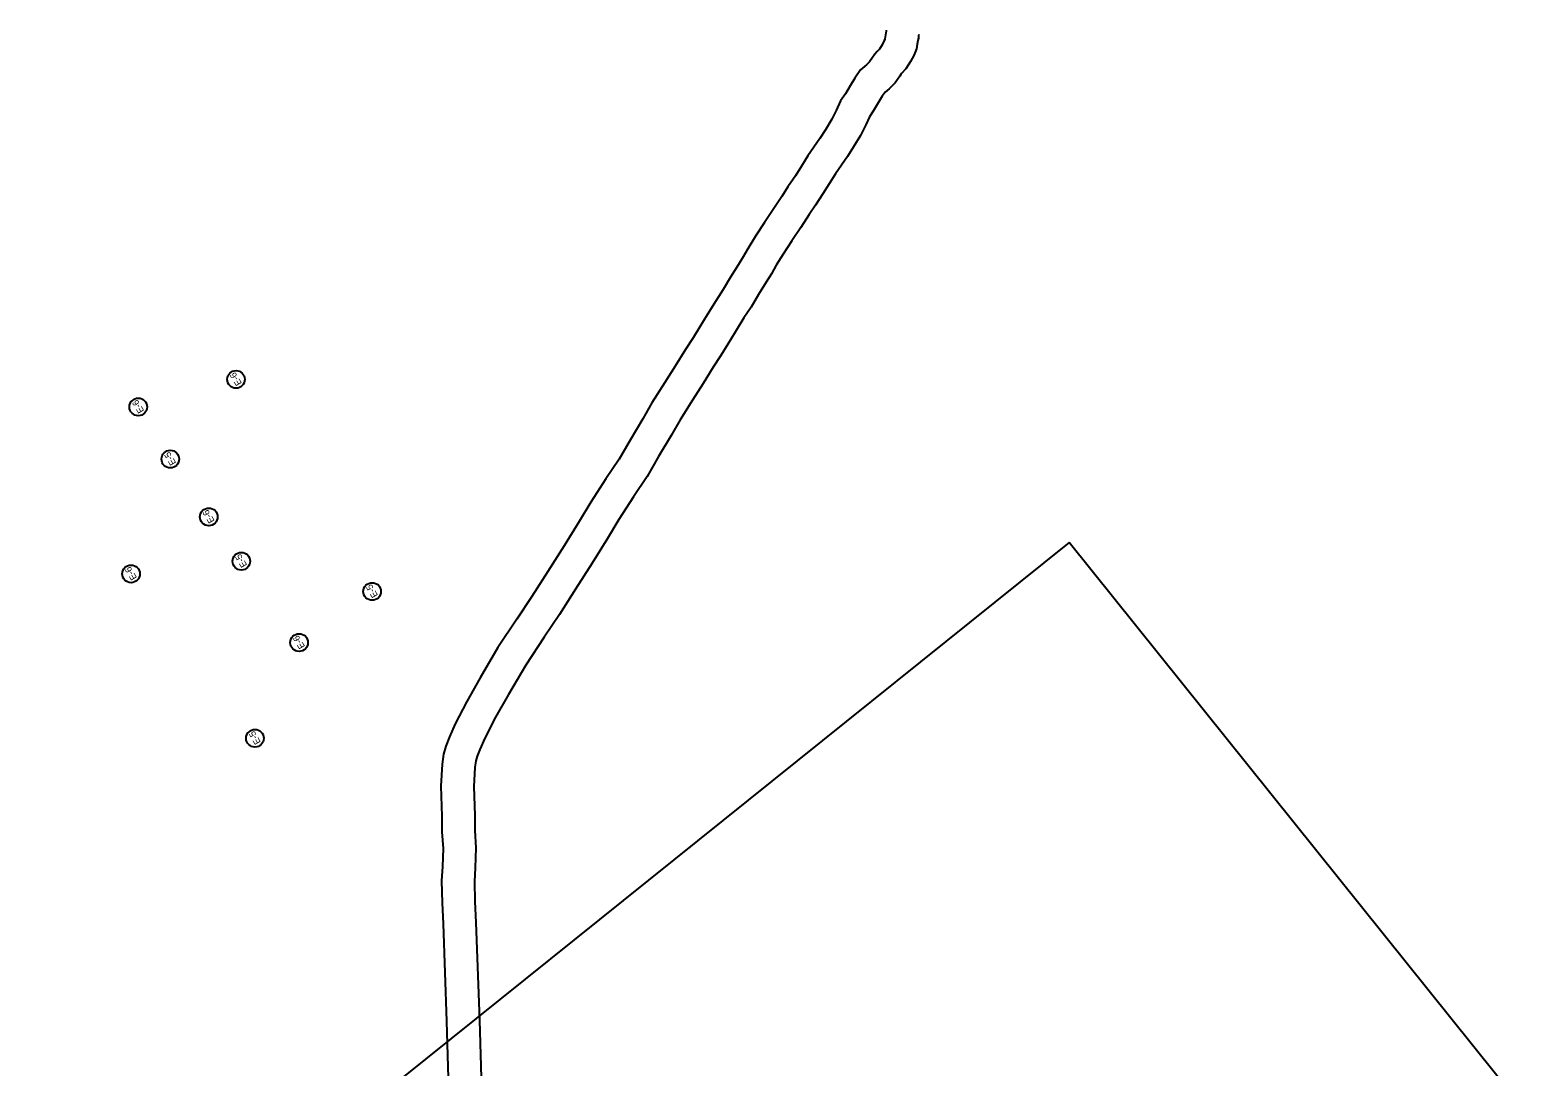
# Model space of a CAD drawing. Extents: x 641687 to 655797, y 406445 to 431088.
# Drawn here: x 646653 to 648945, y 421077 to 422652 of the extents above; entities that cross this region are included whole.
import ezdxf

# ---------------------------------------------------------------- set-up
doc = ezdxf.new("R2010")
doc.units = 0
for name, color, linetype in [('R_Erosion', 7, 'Continuous'), ('R_Erosion_Buffer', 7, 'Continuous'), ('R_No Plot', 7, 'Continuous')]:
    doc.layers.add(name, color=color, linetype=linetype)

msp = doc.modelspace()

# ---------------------------------------------------------------- linework, layer by layer
at = {"layer": 'R_Erosion'}
for centre in [(646965.9, 422121.5), (646817.3, 422079.7), (646866, 422000.4), (646924.5, 421912.6), (646974, 421845.2), (646806.3, 421826), (647172.8, 421799.2), (647061.8, 421721.6), (646994.7, 421576.2)]:
    msp.add_circle(centre, 13.4, dxfattribs=at)
at = {"layer": 'R_Erosion_Buffer'}
for points in [[(647954.3, 422652.2), (647954.1, 422650.2), (647953.8, 422648.4), (647953.2, 422645), (647952.3, 422639.2), (647952.1, 422638.1), (647950.9, 422635.4), (647948.1, 422630), (647943.9, 422623.5), (647940.7, 422619.8), (647936.9, 422615.8), (647933.6, 422610.6), (647929.1, 422604.3), (647924.4, 422599.5), (647915.4, 422591.8), (647906.6, 422579.4), (647899.3, 422567.6), (647892.2, 422555.6), (647885, 422544.7), (647878.3, 422530.1), (647871.6, 422516.9), (647861.8, 422501), (647853.5, 422487.5), (647835.4, 422461.4), (647825.4, 422445.3), (647816.2, 422431), (647804.9, 422413.9), (647795.4, 422399.4), (647782.6, 422379.8), (647769.5, 422359.7), (647755.6, 422339.2), (647743.8, 422320.1), (647737, 422307.6), (647729.6, 422296.1), (647717.6, 422276.7), (647706.3, 422257.9), (647695.8, 422241.6), (647682.3, 422219.7), (647671, 422201.3), (647660.7, 422184.8), (647649.1, 422167), (647633.6, 422141.8), (647617.7, 422116.8), (647598.2, 422085.7), (647584.2, 422061.5), (647565.1, 422029.4), (647548.3, 422000.5), (647528.2, 421970.6), (647505.2, 421935.1), (647487.7, 421905.5), (647464.8, 421868.8), (647439.9, 421829.8), (647415.6, 421791.8), (647392.8, 421757.3), (647364.1, 421714), (647336.8, 421668), (647316.6, 421632.1), (647299, 421598.1), (647290.3, 421578.5), (647284.7, 421564.3), (647281.5, 421551.8), (647279.2, 421536.7), (647277.5, 421503.6), (647278.7, 421457.9), (647278.9, 421433.8), (647280.7, 421408.8), (647279.6, 421381.5), (647278.3, 421359.4), (647279.2, 421326.2), (647280.6, 421294.3), (647286.1, 421146.2), (647289.9, 421008.1)], [(647954.3, 422652.2), (647954.1, 422650.2), (647953.8, 422648.4), (647953.2, 422645), (647952.3, 422639.2), (647952.1, 422638.1), (647950.9, 422635.4), (647948.1, 422630), (647943.9, 422623.5), (647940.7, 422619.8), (647936.9, 422615.8), (647933.6, 422610.6), (647929.1, 422604.3), (647924.4, 422599.5), (647915.4, 422591.8), (647906.6, 422579.4), (647899.3, 422567.6), (647892.2, 422555.6), (647885, 422544.7), (647878.3, 422530.1), (647871.6, 422516.9), (647861.8, 422501), (647853.5, 422487.5), (647835.4, 422461.4), (647825.4, 422445.3), (647816.2, 422431), (647804.9, 422413.9), (647795.4, 422399.4), (647782.6, 422379.8), (647769.5, 422359.7), (647755.6, 422339.2), (647743.8, 422320.1), (647737, 422307.6), (647729.6, 422296.1), (647717.6, 422276.7), (647706.3, 422257.9), (647695.8, 422241.6), (647682.3, 422219.7), (647671, 422201.3), (647660.7, 422184.8), (647649.1, 422167), (647633.6, 422141.8), (647617.7, 422116.8), (647598.2, 422085.7), (647584.2, 422061.5), (647565.1, 422029.4), (647548.3, 422000.5), (647528.2, 421970.6), (647505.2, 421935.1), (647487.7, 421905.5), (647464.8, 421868.8), (647439.9, 421829.8), (647415.6, 421791.8), (647392.8, 421757.3), (647364.1, 421714), (647336.8, 421668), (647316.6, 421632.1), (647299, 421598.1), (647290.3, 421578.5), (647284.7, 421564.3), (647281.5, 421551.8), (647279.2, 421536.7), (647277.5, 421503.6), (647278.7, 421457.9), (647278.9, 421433.8), (647280.7, 421408.8), (647279.6, 421381.5), (647278.3, 421359.4), (647279.2, 421326.2), (647280.6, 421294.3), (647286.1, 421146.2), (647289.9, 421008.1)], [(647954.3, 422652.2), (647954.1, 422650.2), (647953.8, 422648.4), (647953.2, 422645), (647952.3, 422639.2), (647952.1, 422638.1), (647950.9, 422635.4), (647948.1, 422630), (647943.9, 422623.5), (647940.7, 422619.8), (647936.9, 422615.8), (647933.6, 422610.6), (647929.1, 422604.3), (647924.4, 422599.5), (647915.4, 422591.8), (647906.6, 422579.4), (647899.3, 422567.6), (647892.2, 422555.6), (647885, 422544.7), (647878.3, 422530.1), (647871.6, 422516.9), (647861.8, 422501), (647853.5, 422487.5), (647835.4, 422461.4), (647825.4, 422445.3), (647816.2, 422431), (647804.9, 422413.9), (647795.4, 422399.4), (647782.6, 422379.8), (647769.5, 422359.7), (647755.6, 422339.2), (647743.8, 422320.1), (647737, 422307.6), (647729.6, 422296.1), (647717.6, 422276.7), (647706.3, 422257.9), (647695.8, 422241.6), (647682.3, 422219.7), (647671, 422201.3), (647660.7, 422184.8), (647649.1, 422167), (647633.6, 422141.8), (647617.7, 422116.8), (647598.2, 422085.7), (647584.2, 422061.5), (647565.1, 422029.4), (647548.3, 422000.5), (647528.2, 421970.6), (647505.2, 421935.1), (647487.7, 421905.5), (647464.8, 421868.8), (647439.9, 421829.8), (647415.6, 421791.8), (647392.8, 421757.3), (647364.1, 421714), (647336.8, 421668), (647316.6, 421632.1), (647299, 421598.1), (647290.3, 421578.5), (647284.7, 421564.3), (647281.5, 421551.8), (647279.2, 421536.7), (647277.5, 421503.6), (647278.7, 421457.9), (647278.9, 421433.8), (647280.7, 421408.8), (647279.6, 421381.5), (647278.3, 421359.4), (647279.2, 421326.2), (647280.6, 421294.3), (647286.1, 421146.2), (647289.9, 421008.1)], [(648003.9, 422645.6), (648003.6, 422643.6), (648003.2, 422640.3), (648002.4, 422636.5), (648001.6, 422630.9), (648000.2, 422623.6), (647996.2, 422613.9), (647991.3, 422604.8), (647984.1, 422593.5), (647977.7, 422586.2), (647976.3, 422584.7), (647974.9, 422582.5), (647967.8, 422572.4), (647958.7, 422563), (647952.6, 422557.8), (647948.3, 422551.7), (647942.1, 422541.7), (647934.7, 422529.1), (647928.9, 422520.3), (647923.3, 422508.2), (647915.2, 422492.4), (647904.4, 422474.8), (647895.4, 422460.2), (647877.3, 422434.1), (647867.7, 422418.5), (647858, 422403.6), (647846.7, 422386.5), (647837.2, 422372), (647824.4, 422352.4), (647811.1, 422332), (647797.6, 422312), (647787.1, 422295.1), (647780, 422282), (647771.8, 422269.4), (647760.4, 422250.7), (647748.8, 422231.4), (647738, 422214.9), (647724.9, 422193.5), (647713.5, 422175), (647702.9, 422158), (647691.4, 422140.3), (647676, 422115.3), (647660, 422090.1), (647641, 422059.9), (647627.3, 422036.2), (647608.2, 422004.1), (647590.8, 421974), (647570, 421943), (647547.7, 421908.7), (647530.5, 421879.6), (647507.1, 421842.1), (647482, 421802.9), (647457.6, 421764.5), (647434.5, 421729.7), (647406.5, 421687.4), (647380.1, 421642.9), (647360.6, 421608.4), (647344.1, 421576.4), (647336.4, 421559.2), (647332.4, 421548.9), (647330.5, 421541.7), (647329, 421531.6), (647327.6, 421503), (647328.7, 421458.7), (647328.9, 421435.8), (647330.7, 421409.7), (647329.6, 421379.1), (647328.4, 421358.5), (647329.1, 421328), (647330.6, 421296.4), (647336.1, 421147.8), (647340, 421008.1)], [(648003.9, 422645.6), (648003.6, 422643.6), (648003.2, 422640.3), (648002.4, 422636.5), (648001.6, 422630.9), (648000.2, 422623.6), (647996.2, 422613.9), (647991.3, 422604.8), (647984.1, 422593.5), (647977.7, 422586.2), (647976.3, 422584.7), (647974.9, 422582.5), (647967.8, 422572.4), (647958.7, 422563), (647952.6, 422557.8), (647948.3, 422551.7), (647942.1, 422541.7), (647934.7, 422529.1), (647928.9, 422520.3), (647923.3, 422508.2), (647915.2, 422492.4), (647904.4, 422474.8), (647895.4, 422460.2), (647877.3, 422434.1), (647867.7, 422418.5), (647858, 422403.6), (647846.7, 422386.5), (647837.2, 422372), (647824.4, 422352.4), (647811.1, 422332), (647797.6, 422312), (647787.1, 422295.1), (647780, 422282), (647771.8, 422269.4), (647760.4, 422250.7), (647748.8, 422231.4), (647738, 422214.9), (647724.9, 422193.5), (647713.5, 422175), (647702.9, 422158), (647691.4, 422140.3), (647676, 422115.3), (647660, 422090.1), (647641, 422059.9), (647627.3, 422036.2), (647608.2, 422004.1), (647590.8, 421974), (647570, 421943), (647547.7, 421908.7), (647530.5, 421879.6), (647507.1, 421842.1), (647482, 421802.9), (647457.6, 421764.5), (647434.5, 421729.7), (647406.5, 421687.4), (647380.1, 421642.9), (647360.6, 421608.4), (647344.1, 421576.4), (647336.4, 421559.2), (647332.4, 421548.9), (647330.5, 421541.7), (647329, 421531.6), (647327.6, 421503), (647328.7, 421458.7), (647328.9, 421435.8), (647330.7, 421409.7), (647329.6, 421379.1), (647328.4, 421358.5), (647329.1, 421328), (647330.6, 421296.4), (647336.1, 421147.8), (647340, 421008.1)], [(648003.9, 422645.6), (648003.6, 422643.6), (648003.2, 422640.3), (648002.4, 422636.5), (648001.6, 422630.9), (648000.2, 422623.6), (647996.2, 422613.9), (647991.3, 422604.8), (647984.1, 422593.5), (647977.7, 422586.2), (647976.3, 422584.7), (647974.9, 422582.5), (647967.8, 422572.4), (647958.7, 422563), (647952.6, 422557.8), (647948.3, 422551.7), (647942.1, 422541.7), (647934.7, 422529.1), (647928.9, 422520.3), (647923.3, 422508.2), (647915.2, 422492.4), (647904.4, 422474.8), (647895.4, 422460.2), (647877.3, 422434.1), (647867.7, 422418.5), (647858, 422403.6), (647846.7, 422386.5), (647837.2, 422372), (647824.4, 422352.4), (647811.1, 422332), (647797.6, 422312), (647787.1, 422295.1), (647780, 422282), (647771.8, 422269.4), (647760.4, 422250.7), (647748.8, 422231.4), (647738, 422214.9), (647724.9, 422193.5), (647713.5, 422175), (647702.9, 422158), (647691.4, 422140.3), (647676, 422115.3), (647660, 422090.1), (647641, 422059.9), (647627.3, 422036.2), (647608.2, 422004.1), (647590.8, 421974), (647570, 421943), (647547.7, 421908.7), (647530.5, 421879.6), (647507.1, 421842.1), (647482, 421802.9), (647457.6, 421764.5), (647434.5, 421729.7), (647406.5, 421687.4), (647380.1, 421642.9), (647360.6, 421608.4), (647344.1, 421576.4), (647336.4, 421559.2), (647332.4, 421548.9), (647330.5, 421541.7), (647329, 421531.6), (647327.6, 421503), (647328.7, 421458.7), (647328.9, 421435.8), (647330.7, 421409.7), (647329.6, 421379.1), (647328.4, 421358.5), (647329.1, 421328), (647330.6, 421296.4), (647336.1, 421147.8), (647340, 421008.1)]]:
    msp.add_lwpolyline(points, dxfattribs=at)
at = {"layer": 'R_No Plot'}
msp.add_lwpolyline([(648232.3, 421873.9), (646652.9, 420606.2), (646652.9, 420606.2), (648155.3, 418734.6), (649734.6, 420002.3)], close=True, dxfattribs=at)

# ---------------------------------------------------------------- texts
at = {"layer": 'R_Erosion'}
for s, rotation, p in [('E-6', 121.2291, (646975.2, 422115.7)), ('E-6', 121.2291, (646826.6, 422073.8)), ('E-5', 120.3531, (646875.2, 421994.5)), ('E-6', 121.2291, (646933.8, 421906.7)), ('E-5', 120.3531, (646983.1, 421839.3)), ('E-6', 121.5653, (646815.7, 421820.2)), ('E-5', 120.3531, (647182, 421793.3)), ('E-6', 121.2291, (647071.1, 421715.7)), ('E-5', 120.3531, (647003.9, 421570.3))]:
    msp.add_text(s, height=10, rotation=rotation, dxfattribs=at).set_placement(p)

doc.saveas('drawing.dxf')
